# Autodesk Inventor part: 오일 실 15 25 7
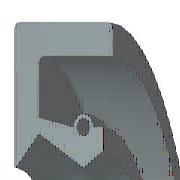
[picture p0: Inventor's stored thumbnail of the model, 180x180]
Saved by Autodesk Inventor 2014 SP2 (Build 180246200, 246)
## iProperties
Created: 2012-02
Part Number: 오일 실 15 25 7
Material: 고무
Description: 오일-실
Document SubType Name: Modeling
Standard: KS B 2804
Designer: mduedu
Standards Organization: KS
Language: ko-KR
Size Designation: D - 15 25 7
Categories: <MemberInstance><Categories><Category DisplayName="샤프트 부품" InternalName="7f7aeb1f-a693-4053-b835-cee3144e0d98" Mnemonic="SHFT"><Category DisplayName="실링" Intern
Density: 0.93 g/cm^3
Appearance: 고무 - 검은색 - 버전 1.1
IsCustomPart: 1
Author: mduedu
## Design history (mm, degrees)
revolve "본체" stored, may be unused: angle "d17" = 90 deg
revolve "스프링1" stored, may be unused: angle "d18" = 90 deg
body "Solid1"
sketch "스케치1"
  geometry: L1 (0, 12.5)-(7, 12.5); L2 (7, 10.75)-(1.75, 10.75); L3 (1.75, 9.25)-(4.9, 7.5); L4 (4.9, 7.5)-(0, 7.5); L5 (0, 0)-(9.586, 0) reference; L6 (4.9, 7.5)-(6.3, 8.375); L7 (0, 18)-(0, -3) reference; L8 (-1.941, 0)-(11.507, 0) reference; L9 (4.2, 9.6)-(1.75, 10.09); L10 (1.75, 10.09)-(1.75, 10.75); L11 (0, 12.5)-(0, 7.588); L12 (4.9, 7.5)-(0, 7.5); L13 (1.75, 9.25)-(0.152, 7.528); L14 (7, 12.5)-(7, 10.75); L15 (5.6, 9.6)-(6.3, 9.6); L16 (6.3, 9.6)-(6.3, 8.375); C1 r 0.455 at (4.9, 9.6); A1 r 0.7 centre (4.9, 9.6) between (5.6, 9.6) and (4.2, 9.6); A2 r 0.088 centre (0.088, 7.588) between (0, 7.588) and (0.152, 7.528); 1 further point
  constraints: 28 end point, 5 horizontal alignment, 5 point on line, 4 point on circle, 4 vertical alignment, 3 centre point, 3 tangent, 2 collinear, 2 horizontal, 2 perpendicular, 1 coincident, 1 parallel
  dimensions: "d0" = 25 diameter of L1 L5 (= SD2); "d1" = 1.75 distance of L1.end L2.start (= SD); "d2" = 0.91 diameter of C1 (= SPDI); "d3" = 1.4 diameter of A1 (= SPDA); "d4" = 15 diameter of L3.end L5 (= NND); "d5" = 18.5 diameter of L3.start L5 (= TKDM); "d7" = 20.18 diameter of L9.end L5 (= TKDM + 0.24 x SWDT); "d8" = 1.75 distance between parallel lines of L11 L10 (= SD); "d9" = 4.9 distance from line of L11 C1.centre (= SPDST); "d10" = 19.2 diameter of C1.centre L5 (= HLDM); "d11" = 0.0875 radius of A2 (= 0.25 x LAB); "d12" = 6.3 distance between parallel lines of L11 L16 (= SDI); "d13" = 16.75 diameter of L6.end L5 (= ABDM); "d14" = 7 distance from line of L11 L1.end (= SWDT)
fillet "모깎기1" dims "d6" = 0.3 (= RR)
other parameters: "SD2" = 25 [user parameter; used in 1 equation term], "SWDT" = 7 [user parameter; used in 2 equation terms], "RR" = 0.3 [user parameter; used in 1 equation term], "SD" = 1.75 [user parameter; used in 2 equation terms], "NND" = 15 [user parameter; used in 1 equation term], "SPDA" = 1.4 [user parameter; used in 1 equation term], "SPDI" = 0.91 [user parameter; used in 1 equation term], "TKDM" = 18.5 [user parameter; used in 2 equation terms], "HLDM" = 19.2 [user parameter; used in 1 equation term], "ABDM" = 16.75 [user parameter; used in 1 equation term], "SDI" = 6.3 [user parameter; used in 1 equation term], "SPDST" = 4.9 [user parameter; used in 1 equation term], "LAB" = 0.35 [user parameter; used in 1 equation term], "d15" = 0, "d16" = 0, "d19" = 0
